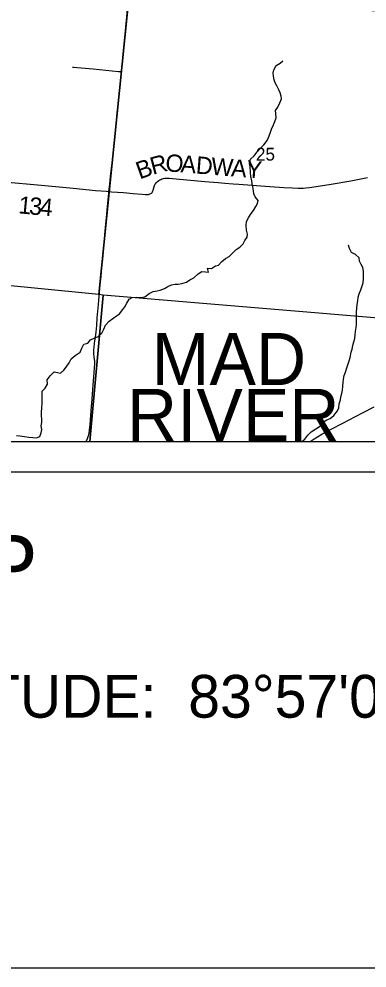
# Model space of a CAD drawing. Extents: x 831 to 1552, y 430 to 870.
# Drawn here: x 1336.5 to 1359.3, y 616.5 to 678.6 of the extents above; entities that cross this region are included whole.
import ezdxf

# ---------------------------------------------------------------- set-up
doc = ezdxf.new("R2010")
doc.units = 0
for name, color, linetype in [('GM_X_Corporation', 7, 'Continuous'), ('GM_X_County_Road', 7, 'Continuous'), ('GM_X_Minor_River', 7, 'Continuous'), ('GM_X_Section_Text', 7, 'Continuous'), ('GM_X_Township_Road', 7, 'Continuous'), ('GM_X_Township_Road_Text', 7, 'Continuous'), ('GM_X_Township_Text', 7, 'Continuous'), ('SH_Data', 7, 'Continuous'), ('SH_Text', 7, 'Continuous')]:
    doc.layers.add(name, color=color, linetype=linetype)

msp = doc.modelspace()

# ---------------------------------------------------------------- linework, layer by layer
at = {"layer": 'GM_X_Corporation'}
msp.add_lwpolyline([(1250.766, 650.938), (1386.766, 650.938), (1386.766, 724.317)], dxfattribs=at)
for points in [[(1323.531, 682.478), (1343.776, 680.603), (1341.746, 660.547), (1321.979, 662.503), (1321.541, 662.548)], [(1343.776, 680.603), (1363.462, 678.79), (1361.646, 658.883), (1342.018, 660.52), (1341.746, 660.547)], [(1320.907, 650.938), (1341.147, 650.938), (1342.018, 660.52), (1341.746, 660.547), (1321.979, 662.503)], [(1341.147, 650.938), (1361.329, 650.938), (1361.881, 658.872), (1361.646, 658.883), (1342.018, 660.52)]]:
    msp.add_lwpolyline(points, close=True, dxfattribs=at)
at = {"layer": 'GM_X_County_Road'}
msp.add_lwpolyline([(1355.594, 650.938), (1355.778, 651.053), (1356.359, 651.414), (1356.629, 651.569), (1356.957, 651.746), (1357.732, 652.142), (1358.559, 652.569), (1359.057, 652.825), (1359.774, 653.196)], dxfattribs=at)
at = {"layer": 'GM_X_Minor_River'}
for points in [[(1351.403, 665.068), (1351.422, 665.328), (1351.57, 665.608), (1351.717, 665.857), (1351.871, 666.052), (1352.027, 666.316), (1352.135, 666.512), (1352.176, 666.702), (1351.996, 666.954), (1351.908, 667.153), (1351.88, 667.343), (1351.83, 667.594), (1351.794, 667.799), (1351.766, 667.997), (1351.694, 668.271), (1351.674, 668.537), (1351.664, 668.932), (1351.605, 669.138), (1351.677, 669.411), (1351.923, 669.62), (1352.116, 669.899), (1352.324, 670.14), (1352.555, 670.349), (1352.763, 670.628), (1352.857, 670.832), (1352.959, 671.112), (1353.061, 671.384), (1353.186, 671.648), (1353.28, 671.867), (1353.352, 672.125), (1353.347, 672.398), (1353.319, 672.596), (1353.474, 672.822), (1353.607, 673.093), (1353.716, 673.35), (1353.688, 673.541), (1353.615, 673.754), (1353.534, 673.952), (1353.415, 674.22), (1353.304, 674.411), (1353.238, 674.601), (1353.18, 674.853), (1353.16, 675.058), (1353.2, 675.262), (1353.371, 675.534), (1353.616, 675.69), (1353.808, 675.84)], [(1336.347, 651.327), (1336.574, 651.301), (1336.883, 651.252), (1337.147, 651.219), (1337.419, 651.192), (1337.668, 651.167), (1337.881, 651.263), (1337.96, 651.497), (1338, 651.708), (1337.973, 651.951), (1337.998, 652.186), (1338.008, 652.398), (1337.988, 652.61), (1337.976, 652.83), (1338.003, 653.148), (1338.029, 653.428), (1338.04, 653.754), (1338.028, 653.959), (1338.031, 654.224), (1338.23, 654.433), (1338.369, 654.689), (1338.365, 654.962), (1338.558, 655.24), (1338.81, 655.487), (1339.044, 655.454), (1339.24, 655.399), (1339.454, 655.593), (1339.593, 655.796), (1339.793, 656.074), (1339.932, 656.345), (1340.199, 656.561), (1340.52, 656.785), (1340.621, 657.034), (1340.768, 657.297), (1341.033, 657.377), (1341.195, 657.595), (1341.445, 657.69), (1341.696, 657.808), (1341.948, 658.018), (1342.065, 658.289), (1342.189, 658.553), (1342.427, 658.8), (1342.671, 658.979), (1342.892, 659.165), (1343.091, 659.299), (1343.321, 659.562), (1343.452, 659.757), (1343.568, 659.991), (1343.73, 660.246), (1343.92, 660.358), (1344.185, 660.385), (1344.502, 660.351), (1344.76, 660.408), (1345.05, 660.624), (1345.301, 660.742), (1345.566, 660.792), (1345.771, 660.835), (1346.037, 660.946), (1346.257, 661.072), (1346.493, 661.19), (1346.743, 661.233), (1346.94, 661.238), (1347.19, 661.28), (1347.478, 661.368), (1347.707, 661.509), (1347.958, 661.634), (1348.24, 661.896), (1348.492, 662.052), (1348.733, 662.027), (1348.937, 662.017), (1348.865, 662.275), (1349.122, 662.257), (1349.396, 662.42), (1349.585, 662.463), (1349.793, 662.711), (1350.052, 662.92), (1350.281, 663.046), (1350.51, 663.263), (1350.74, 663.495), (1350.983, 663.644), (1351.198, 663.861), (1351.314, 664.079), (1351.46, 664.305), (1351.485, 664.509), (1351.428, 664.767), (1351.403, 665.068)], [(1357.913, 655.481), (1357.968, 655.692), (1358.062, 655.957), (1358.149, 656.213), (1358.212, 656.425), (1358.284, 656.78), (1358.339, 656.976), (1358.395, 657.218), (1358.451, 657.445), (1358.507, 657.679), (1358.54, 657.914), (1358.55, 658.133), (1358.607, 658.398), (1358.617, 658.61), (1358.628, 658.882), (1358.634, 659.375), (1358.653, 659.678), (1358.663, 659.875), (1358.704, 660.155), (1358.737, 660.374), (1358.792, 660.601), (1358.909, 660.857), (1358.979, 661.053), (1359.058, 661.31), (1359.092, 661.59), (1359.08, 661.855), (1359.075, 662.083), (1359.033, 662.326), (1358.93, 662.516), (1358.827, 662.745), (1358.791, 662.958), (1358.56, 663.172), (1358.297, 663.297), (1358.156, 663.556), (1358.099, 663.792)], [(1355.044, 650.938), (1355.243, 651.095), (1355.435, 651.351), (1355.665, 651.56), (1355.962, 651.754), (1356.274, 651.962), (1356.467, 652.225), (1356.68, 652.351), (1356.893, 652.447), (1357.144, 652.641), (1357.375, 652.934), (1357.461, 653.145), (1357.494, 653.387), (1357.573, 653.659), (1357.598, 653.856), (1357.669, 654.067), (1357.701, 654.286), (1357.72, 654.559), (1357.746, 654.801), (1357.771, 655.005), (1357.827, 655.262), (1357.913, 655.481)]]:
    msp.add_lwpolyline(points, dxfattribs=at)
at = {"layer": 'GM_X_Township_Road'}
for points in [[(1343.225, 675.139), (1343.361, 676.513), (1343.449, 677.378), (1343.506, 678.057), (1343.577, 678.732), (1343.629, 679.237), (1343.66, 679.599), (1343.736, 680.215), (1343.825, 680.955), (1343.945, 681.879), (1344.022, 682.495), (1344.073, 682.99), (1344.092, 683.128)], [(1340.024, 675.442), (1340.085, 675.437), (1340.577, 675.39), (1341.376, 675.313), (1343.038, 675.156), (1343.225, 675.139)], [(1342.402, 667.293), (1342.457, 667.743), (1342.518, 668.298), (1342.592, 668.977), (1342.653, 669.533), (1342.724, 670.212), (1342.858, 671.508), (1342.948, 672.435), (1343.051, 673.361), (1343.108, 673.917), (1343.161, 674.472), (1343.208, 674.967), (1343.225, 675.139)], [(1335.78, 667.913), (1337.731, 667.725), (1339.39, 667.569), (1340.054, 667.506), (1341.534, 667.365), (1342.25, 667.306), (1342.402, 667.293)], [(1342.402, 667.293), (1342.562, 667.281), (1343.364, 667.22), (1343.983, 667.166), (1344.581, 667.111), (1344.794, 667.095), (1344.885, 667.091), (1344.93, 667.093), (1344.987, 667.103), (1345.033, 667.113), (1345.094, 667.133), (1345.145, 667.162), (1345.188, 667.192), (1345.228, 667.228), (1345.262, 667.277), (1345.291, 667.329), (1345.312, 667.385), (1345.368, 667.626), (1345.388, 667.687), (1345.416, 667.745), (1345.45, 667.799), (1345.498, 667.861), (1345.538, 667.904), (1345.589, 667.953), (1345.664, 668.009), (1345.733, 668.052), (1345.796, 668.087), (1345.861, 668.115), (1345.922, 668.135), (1345.989, 668.151), (1346.076, 668.166), (1346.173, 668.174), (1346.34, 668.176), (1347.024, 668.107), (1347.519, 668.06), (1348.689, 667.96), (1349.555, 667.885), (1349.988, 667.849), (1350.545, 667.801), (1350.916, 667.771), (1352.956, 667.622), (1353.882, 667.567), (1354.439, 667.534), (1354.811, 667.519), (1355.12, 667.52), (1355.305, 667.529), (1355.551, 667.554), (1355.981, 667.617), (1356.961, 667.777), (1358.244, 668.004), (1359.343, 668.205)], [(1340.908, 650.938), (1341.002, 651.136), (1341.046, 651.25), (1341.082, 651.368), (1341.109, 651.488), (1341.137, 651.67), (1341.172, 652.04), (1341.259, 653.217), (1341.299, 653.712), (1341.376, 654.641), (1341.414, 655.136), (1341.466, 655.754), (1341.478, 656.001), (1341.475, 656.186), (1341.466, 656.308), (1341.442, 656.492), (1341.419, 656.678), (1341.413, 656.803), (1341.416, 656.928), (1341.433, 657.115), (1341.466, 657.362), (1341.535, 657.79), (1341.569, 658.098), (1341.604, 658.53), (1341.639, 659.025), (1341.712, 659.89), (1341.765, 660.446), (1341.841, 661.188), (1341.894, 661.744), (1341.942, 662.301), (1341.996, 662.858), (1342.044, 663.352), (1342.088, 663.909), (1342.158, 664.714), (1342.237, 665.58), (1342.304, 666.322), (1342.388, 667.188), (1342.402, 667.293)]]:
    msp.add_lwpolyline(points, dxfattribs=at)
at = {"layer": 'SH_Data'}
for p, q in [((1250.766, 650.938), (1386.766, 650.938)), ((1248.766, 648.938), (1388.766, 648.938)), ((1362.766, 616.471), (1298.64, 616.471))]:
    msp.add_line(p, q, dxfattribs=at)

# ---------------------------------------------------------------- texts
at = {"layer": 'GM_X_Section_Text'}
msp.add_text('25', height=0.8371, rotation=0.00001, dxfattribs=at).set_placement((1352.037, 669.318))
at = {"layer": 'GM_X_Township_Road_Text'}
for s, rotation, p in [('R', 14.78597, (1345.274, 668.386)), ('O', 356.40231, (1346.081, 668.615)), ('A', 355.49289, (1347.074, 668.553)), ('B', 19.68165, (1344.42, 668.08)), ('D', 355.48563, (1348.071, 668.474)), ('W', 355.48651, (1349.068, 668.395)), ('A', 355.4881, (1350.381, 668.292)), ('Y', 355.48563, (1351.378, 668.213)), ('1', 354.48751, (1336.436, 665.874)), ('3', 354.72496, (1337.138, 665.807)), ('4', 354.79059, (1337.836, 665.742))]:
    msp.add_text(s, height=1.136, rotation=rotation, dxfattribs=at).set_placement(p)
at = {"layer": 'GM_X_Township_Text'}
for s, p in [('MAD', (1345.196, 654.63)), ('RIVER', (1343.58, 650.962))]:
    msp.add_text(s, height=3.4091, rotation=0.00001, dxfattribs=at).set_placement(p)
at = {"layer": 'SH_Text'}
for s, height, p in [('LOCATION MAP', 4, (1297.305, 640.813)), ('CLA-40-0530     LATITUDE:  39°55\'03"     LONGITUDE:  83°57\'00"', 2.8, (1252.705, 632.855))]:
    msp.add_text(s, height=height, dxfattribs=at).set_placement(p)

doc.saveas('drawing.dxf')
